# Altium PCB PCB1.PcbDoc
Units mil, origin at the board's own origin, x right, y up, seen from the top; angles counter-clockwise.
Board outline 3149.61 x 3937.01 mil, 2 copper layers (Top Layer, Bottom Layer); 80 components, 52 nets, 339 pads, 13 vias.
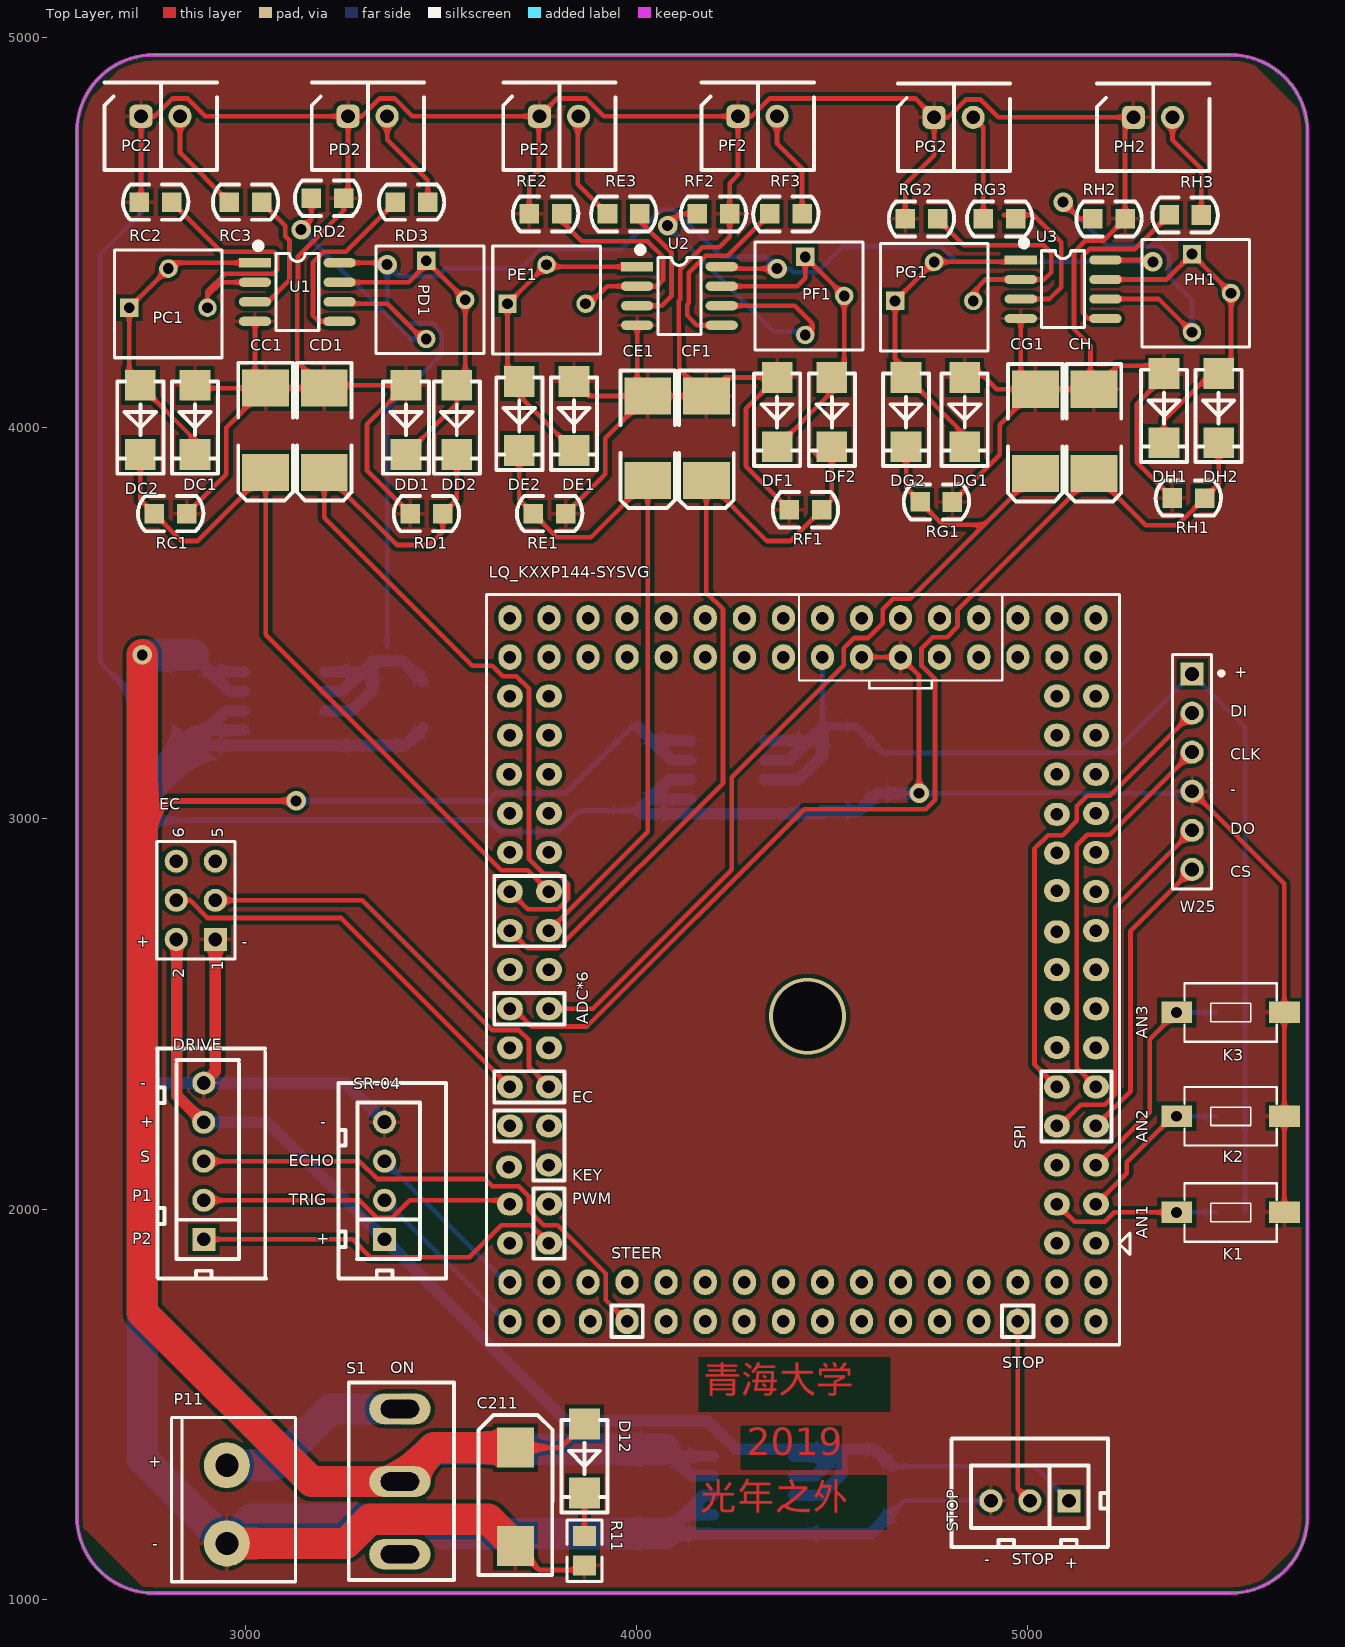
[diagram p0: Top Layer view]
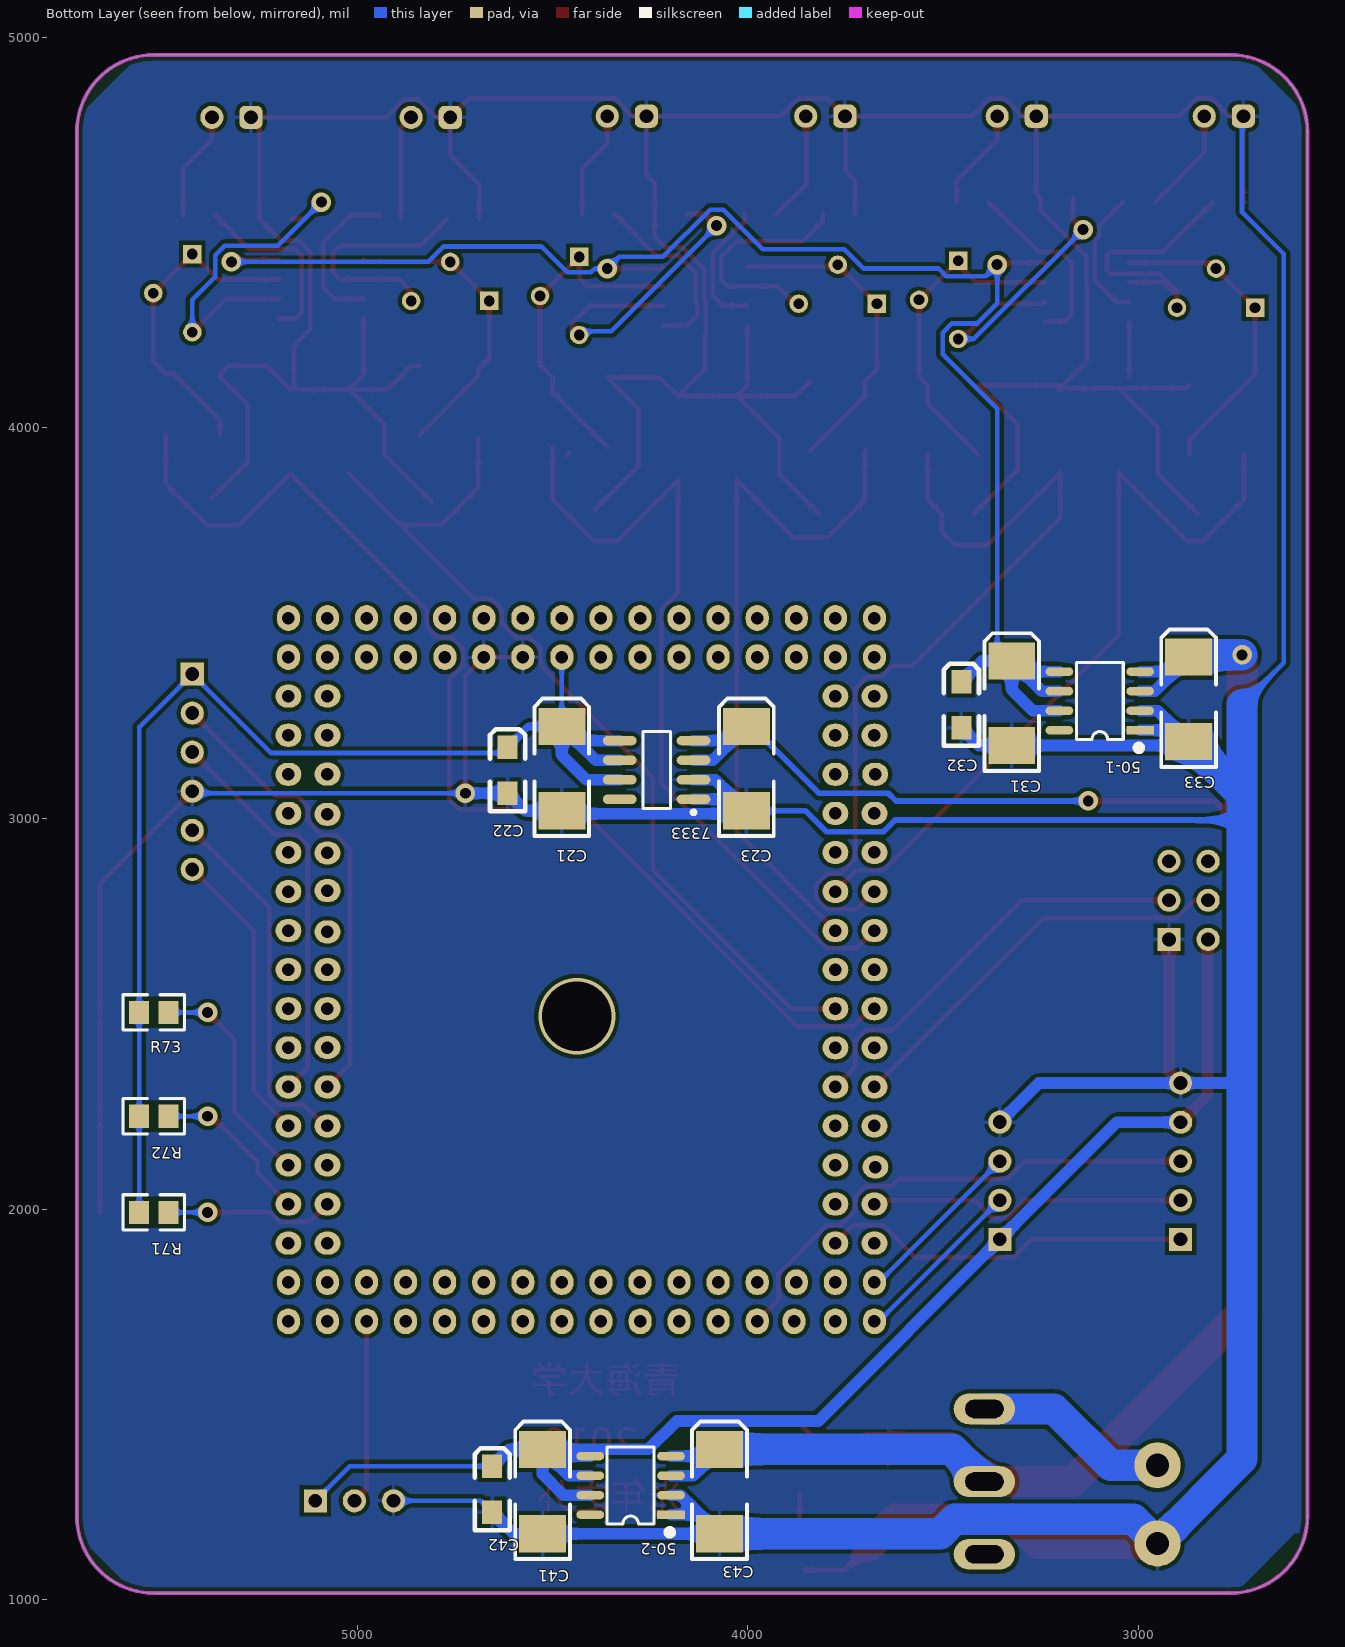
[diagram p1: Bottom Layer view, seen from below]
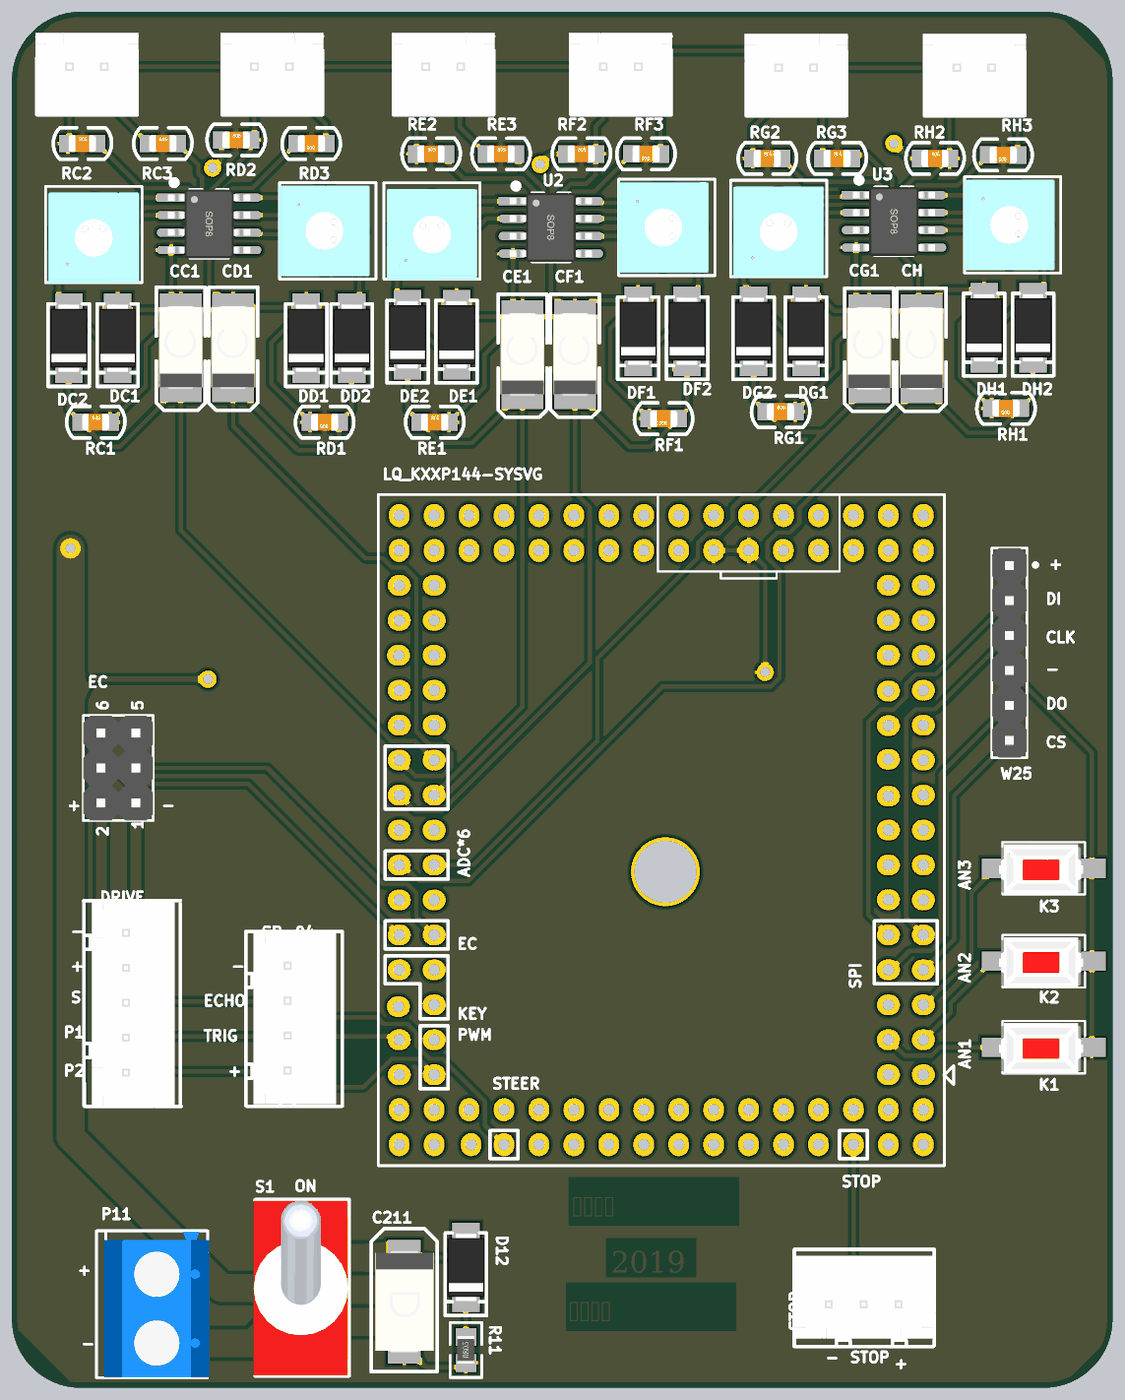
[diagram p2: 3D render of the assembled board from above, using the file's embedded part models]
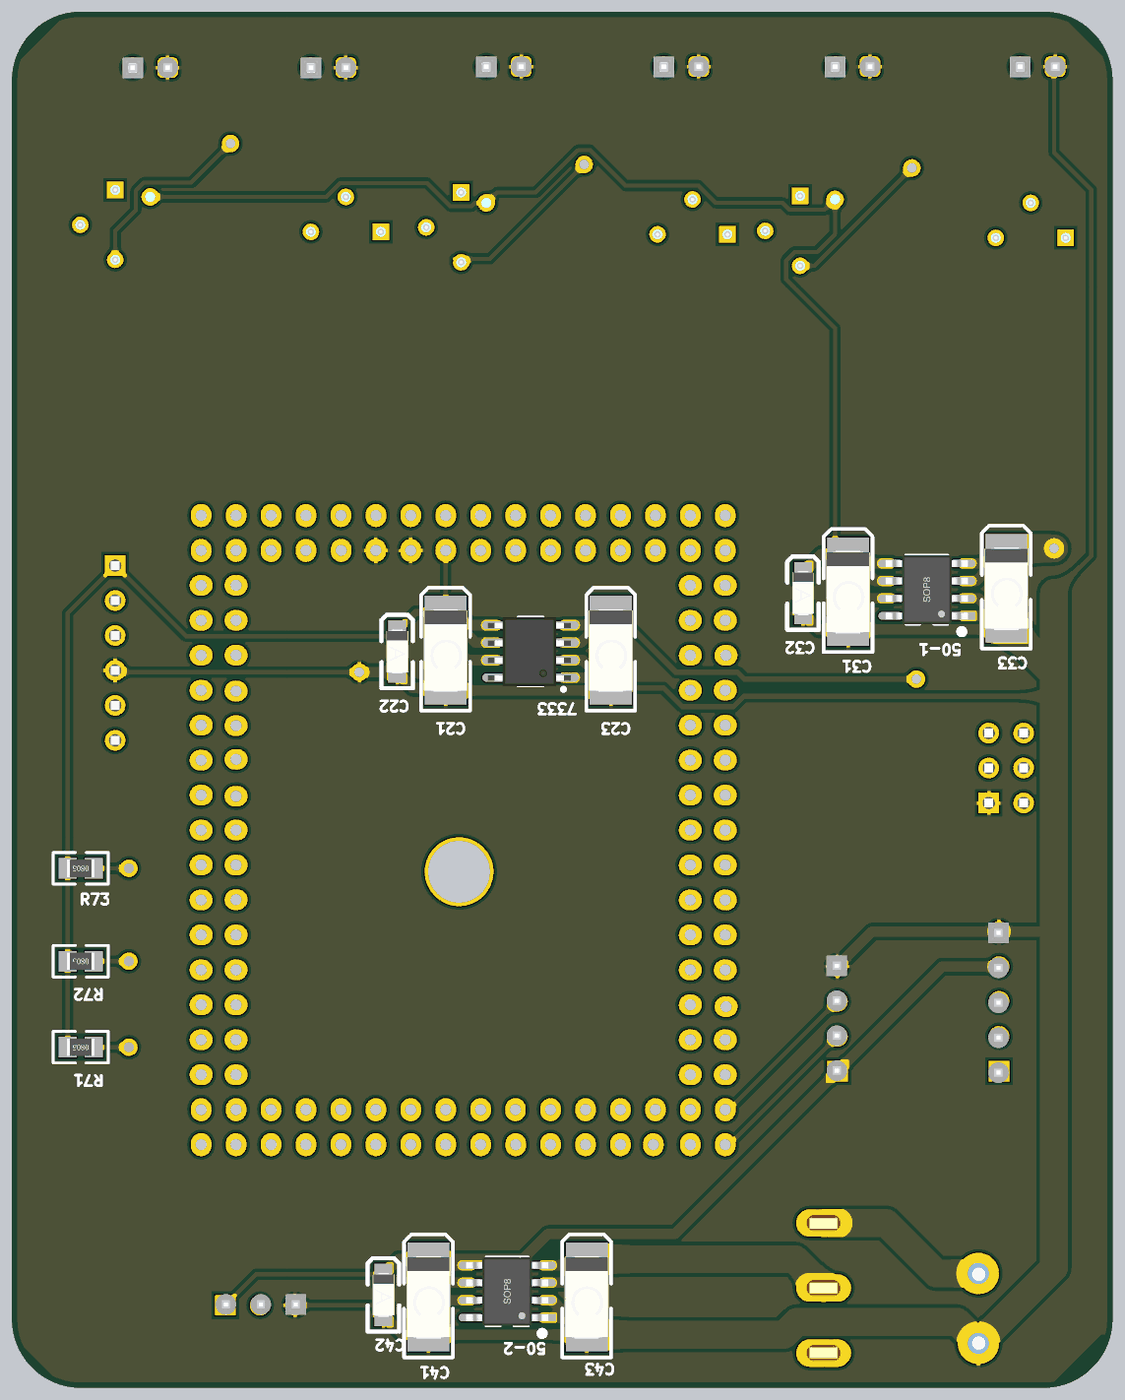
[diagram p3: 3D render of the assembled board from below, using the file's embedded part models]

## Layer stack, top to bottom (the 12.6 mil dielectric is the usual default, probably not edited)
Top Solder: solder mask 0.4, Solder Resist, Dk 3.5
Top Layer: signal copper 1.4
Dielectric 1: dielectric 12.6, FR-4, Dk 4.8
Bottom Layer: signal copper 1.4
Bottom Solder: solder mask 0.4, Solder Resist, Dk 3.5

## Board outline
2567.68,1214.09 2567.68,4757.4 cw(c2764.53,4757.4) 2764.53,4954.25 5520.43,4954.25 cw(c5520.43,4757.4) 5717.28,4757.4 5717.28,1214.09 cw(c5520.43,1214.09) 5520.43,1017.24 2764.53,1017.24 cw(c2764.53,1214.09)

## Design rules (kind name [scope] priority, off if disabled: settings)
Clearance [All] p1: gap=10
HoleSize [All] p1: absolutevalues=TRUE maxlimit=350 minlimit=1 maxpercent=80.000 minpercent=20.000
MinimumSolderMaskSliver [All] p1 off: minsoldermaskwidth=10
PolygonConnect [All] p1: connectstyle=Relief reliefconductorwidth=10 reliefentries=4 polygonreliefangle="90 Angle" airgapwidth=10
RoutingVias [All] p1: holewidth=28 width=50 viastyle="Through Hole" minholewidth=28 minwidth=50 maxholewidth=28 maxwidth=50
SilkToBoardRegionClearance [All] p1 off:
SilkToSilkClearance [All] p1 off: silktosilkclearance=10
SilkToSolderMaskClearance [IsPad] p1 off: minsilkscreentomaskgap=10 clearancetoexposedcopper=TRUE
SolderMaskExpansion [All] p1: expansion=4
Width [All] p1: maxlimit=100 minlimit=8 preferedwidth=12
25 further rules are at their usual default settings.

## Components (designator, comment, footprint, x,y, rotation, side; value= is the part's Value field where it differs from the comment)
50-1 "7350" SOP8_N 3099.17,3300.71 r0 bottom locked
50-2 "7350" SOP8_N 4299.96,1292.83 r0 bottom locked
7333 "7333" SO8_N 4233.43,3124.06 r0 bottom locked
AN1 "Button" SMT4*6*2.5 5520.43,1991.65 r180 top locked
AN2 "Button" SMT4*6*2.5 5520.43,2237.72 r180 top locked
AN3 "Button" SMT4*6*2.5 5520.43,2503.46 r180 top locked
C21 "Cap Pol3" C6032 4477.13,3123.54 r270 bottom locked
C22 "Cap Pol3" C3216 4614.92,3123.54 r270 bottom locked
C23 "Cap Pol3" C6032 4004.69,3123.54 r270 bottom locked
C31 "Cap Pol3" C6032 3325.55,3290.87 r270 bottom locked
C32 "Cap Pol3" C3216 3453.5,3290.87 r270 bottom locked
C33 "Cap Pol3" C6032 2872.8,3300.71 r270 bottom locked
C41 "Cap Pol3" C6032 4526.34,1273.15 r270 bottom locked
C42 "Cap Pol3" C3216 4654.29,1282.99 r270 bottom locked
C43 "Cap Pol3" C6032 4073.58,1273.15 r270 bottom locked
C211 "Cap Pol3" C7343 3689.72,1263.31 r270 top locked
CC1 "Cap Pol3" C6032 3051.77,3997.24 r90 top
CD1 "Cap Pol3" C6032 3201.77,3997.24 r90 top
CE1 "Cap Pol3" C6032 4029.77,3977.24 r90 top
CF1 "Cap Pol3" C6032 4179.77,3977.24 r90 top
CG1 "Cap Pol3" C6032 5021.77,3994.45 r90 top
CH "Cap Pol3" C6032 5171.77,3994.45 r90 top
D12 "LED1" SMA 3866.89,1361.73 r270 top locked
DC1 "4148" SMA 2870,4020 r270 top
DC2 "4148" SMA 2730,4020 r270 top
DD1 "4148" SMA 3410,4020 r270 top
DD2 "4148" SMA 3540,4020 r270 top
DE1 "4148" SMA 3840,4030 r270 top
DE2 "4148" SMA 3700,4030 r270 top
DF1 "4148" SMA 4360,4040 r270 top
DF2 "4148" SMA 4500,4040 r270 top
DG1 "4148" SMA 4840,4040 r270 top
DG2 "4148" SMA 4690,4040 r270 top
DH1 "4148" SMA 5350,4050 r270 top
DH2 "4148" SMA 5490,4050 r270 top
DRIVE "Header 5" HX2.54-5 2892.48,1922.76 r90 top locked
EC "Header 3X2" HDR2X3 2922.01,2690.47 r90 top locked
LQ_KXXP144-SYSVG "LQ_KXXP144-SYSVG" LQ_KXXP144-SYSVG 5175.94,1912.91 r90 top locked
P11 "Header 2" 2PIN-5.08B 2951.54,1144.41 r90 top locked
PC1 "RPot" VR_B1 2801.77,4297.24 r0 top
PC2 "Header 2" HX2.54-2 2731.77,4797.24 r0 top
PD1 "RPot" VR_B1 3451.77,4327.24 r270 top
PD2 "Header 2" HX2.54-2 3261.77,4797.24 r0 top
PE1 "RPot" VR_B1 3769.77,4307.24 r0 top
PE2 "Header 2" HX2.54-2 3751.77,4797.24 r0 top
PF1 "RPot" VR_B1 4421.77,4337.24 r270 top
PF2 "Header 2" HX2.54-2 4259.77,4797.24 r0 top
PG1 "RPot" VR_B1 4761.77,4314.45 r0 top
PG2 "Header 2" HX2.54-2 4761.77,4794.45 r0 top
PH1 "RPot" VR_B1 5411.77,4344.45 r270 top
PH2 "Header 2" HX2.54-2 5271.77,4794.45 r0 top
R11 "Res3" R0805 3866.89,1125.51 r90 top locked
R71 "Res3" R0805 5520.43,1991.65 r0 bottom locked
R72 "Res3" R0805 5520.43,2237.72 r0 bottom locked
R73 "Res3" R0805 5520.43,2503.46 r0 bottom locked
RC1 "Res Semi" C0805 2760,3780 r0 top
RC2 "Res Semi" C0805 2721.77,4577.24 r0 top
RC3 "Res Semi" C0805 2951.77,4577.24 r0 top
RD1 "Res Semi" C0805 3510,3780 r180 top
RD2 "Res Semi" C0805 3161.77,4587.24 r0 top
RD3 "Res Semi" C0805 3471.77,4577.24 r180 top
RE1 "Res Semi" C0805 3730,3780 r0 top
RE2 "Res Semi" C0805 3719.77,4547.24 r0 top
RE3 "Res Semi" C0805 3919.77,4547.24 r0 top
RF1 "Res Semi" C0805 4480,3790 r180 top
RF2 "Res Semi" C0805 4149.77,4547.24 r0 top
RF3 "Res Semi" C0805 4429.77,4547.24 r180 top
RG1 "Res Semi" C0805 4720,3810 r0 top
RG2 "Res Semi" C0805 4681.77,4534.45 r0 top
RG3 "Res Semi" C0805 4881.77,4534.45 r0 top
RH1 "Res Semi" C0805 5460,3820 r180 top
RH2 "Res Semi" C0805 5161.77,4534.45 r0 top
RH3 "Res Semi" C0805 5451.77,4544.45 r180 top
S1 "SW-SPST" SW-TO3 3394.45,1302.68 r180 top locked
SR-04 "Header 4" HX2.54-4 3355.08,1922.76 r90 top locked
STOP "Header 3" HX2.54-3 5107.05,1253.46 r180 top locked
U1 "LM358" SOP8_M 3131.77,4347.24 r0 top
U2 "LM358" SOP8_M 4109.77,4337.24 r0 top
U3 "LM358" SOP8_M 5091.77,4354.45 r0 top
W25 "MHDR1X6" HDR1X6 5422.01,3369.61 r270 top locked

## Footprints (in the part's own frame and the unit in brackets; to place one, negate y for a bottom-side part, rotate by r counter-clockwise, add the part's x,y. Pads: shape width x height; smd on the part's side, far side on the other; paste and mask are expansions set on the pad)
2PIN-5.08B [mm] "3A"
  round 3 hole 1.5: 1(0,0) 2(5.08,0)
  silkscreen extent -2.49,-4.47 8.18,3.61, body extent -2.48,-4.58 8.12,3.02, height 10
C0805 [mil]
  rect 50x50 smd: 1(6,0) 2(88.7,-0.1)
  silkscreen extent -36,-45 131,45, body extent 8,-24 87,25, height 30
C3216 [mil] "A型/1206"
  rect 60x51.18 smd: 1(-59,0) 2(59,0)
  silkscreen extent -105,-45 105,45, body extent -63,-31 63,32, height 63
C6032 [mil] "C型"
  rect 95x120 smd: 1(-112,1) 2(104,1)
  silkscreen extent -183,-69 169,71, body extent -121,-62 115,64, height 102
C7343 [mm] "D型"
  rect 2.6x2.4 smd: 1(-3.202,0.007) 2(3.198,0.007)
  silkscreen extent -5.32,-2.39 5.08,2.41, body extent -3.65,-2.12 3.65,2.18, height 2.9
HDR1X6 [mm] "Connector; Header; 6 Position"
  rect 1.5x1.5 hole 0.9: 1(0,0)
  round 1.5 hole 0.9: 2(2.54,0) 3(5.08,0) 4(7.62,0) 5(10.16,0) 6(12.7,0)
  silkscreen extent -1.27,-1.27 13.97,2.04, body extent -1.27,-1.27 13.97,1.27, height 8.54
HDR2X3 [mm] "Connector; Header; 3x2 Position"
  rect 1.5x1.5 hole 0.9: 1(0,0)
  round 1.5 hole 0.9: 2(0,2.54) 3(2.54,0) 4(2.54,2.54) 5(5.08,0) 6(5.08,2.54)
  silkscreen extent -1.27,-1.27 6.35,3.81, body extent -1.27,-1.27 6.35,3.81, height 8.54
HX2.54-2 [mm] "两针白色插座（已加焊）"
  rrect50% 1.5x1.5 hole 0.9: 1(0,0)
  round 1.5 hole 0.9: 2(2.54,0)
  silkscreen extent -2.36,-3.5 4.94,2.2, body extent -2.48,-3.55 5.02,2.45, height 7
HX2.54-3 [mm]
  rect 1.5x1.5 hole 0.9: 1(0,0)
  round 1.5 hole 0.9: 2(2.54,0) 3(5.08,0)
  silkscreen extent -2.54,-4.06 7.63,3, body extent -2.41,-3.58 7.59,2.42, height 7
HX2.54-4 [mm]
  rect 1.5x1.5 hole 0.9: 1(0,0)
  round 1.5 hole 0.9: 2(2.54,0) 3(5.08,0) 4(7.62,0)
  silkscreen extent -2.54,-4 10.16,3, body extent -2.4,-3.56 10.12,2.44, height 7
HX2.54-5 [mm]
  rect 1.5x1.5 hole 0.9: 1(0,0)
  round 1.5 hole 0.9: 2(2.54,0) 3(5.08,0) 4(7.607,0.006) 5(10.16,0)
  silkscreen extent -2.55,-4.06 12.42,3.05, body extent -2.56,-3.56 12.52,2.44, height 7.51
LQ_KXXP144-SYSVG [mil]
  oval 59x66 hole 32: 1(0,0) 2(0,100) 3(100,0) 4(100,100) 5(200,0) 6(200,100) 7(300,0) 8(300,100) 9(400,0) 10(400,100) 11(500,0) 12(500.79,100) 13(600,0) 14(600,100) 15(700,0) 16(700,100) 17(800,0) 18(796.85,100) 19(900,0) 20(902.36,100) 21(1000,0) 22(998.82,100) 23(1100,0) 24(1097.64,100) 25(1200,0) 26(1200.39,100) 27(1300,0) 28(1300,100) 29(1400,0) 30(1400.39,100) 63(1400,1500) 64(1400,1400) 65(1300,1500) 66(1300,1400) 67(1200,1501.97) 68(1200,1400) 69(1100,1500) 70(1100,1400) 71(1000,1500) 72(1000,1400) 73(900,1500) 74(900,1400) 75(800,1500) 76(800,1400) 77(700,1500) 78(700,1400) 79(600,1500) 80(600,1400) 81(500,1500) 82(500,1400) 83(400,1500) 84(400,1400) 85(300,1500) 86(300,1400) 87(194.88,1502.36) 88(200,1400) 89(100,1500) 90(100,1400) 91(0,1500) 92(0,1400)
  oval 66x59 hole 32: 31(1500,0) 32(1600,0) 33(1500,100) 34(1600,100) 35(1500,200) 36(1600,200) 37(1500,300) 38(1600,300) 39(1500,400.79) 40(1600,400) 41(1500,500) 42(1600,500.39) 43(1500,600) 44(1600,600) 45(1500,700) 46(1600,700) 47(1500,800) 48(1600,800) 49(1500,900) 50(1600,900) 51(1500,1000) 52(1600,1000) 53(1500,1100) 54(1600,1100) 55(1500,1200) 56(1600,1200) 57(1500,1300) 58(1600,1300) 59(1500,1400) 60(1600,1400) 61(1500,1500) 62(1600,1500) 93(-100,1500) 94(-200,1500) 95(-100,1400) 96(-200,1400) 97(-100,1300) 98(-200,1294.09) 99(-100,1200) 100(-200,1200) 101(-100,1100) 102(-200,1100) 103(-100,1000) 104(-200,1000) 105(-100,899.61) 106(-200,900.39) 107(-100,800) 108(-200,800) 109(-100,700) 110(-200,700) 111(-100,600) 112(-200,600) 113(-100,500) 114(-200,500) 115(-100,400) 116(-200,400) 117(-100,300) 118(-200,300) 119(-100,200) 120(-200,200) 121(-100,100) 122(-200,100) 123(-100,0) 124(-200,0)
  silkscreen extent -260,-87 1660,1560
R0805 [mm]
  rect 1.3x1.5 smd: 1(-0.95,0) 2(0.95,0)
  silkscreen extent -2,-1.15 2,1.15, body extent -1,-0.63 1,0.63, height 0.55
SMA [mm]
  rect 2x2 smd: 1(-2.25,0) 2(2.25,0)
  silkscreen extent -2.5,-1.5 3.5,1.5, body extent -2.5,-1.35 2.5,1.35, height 2.15
SMT4*6*2.5 [mm]
  rect 2x1.4 smd: 1(-3.5,0) 2(3.5,0)
  silkscreen extent -3,-1.9 3,1.9, body extent -2.85,-1.75 3.25,1.95, height 2.5
SO8_N [mm] "SOIC, 8-Leads, Body 4.9x3.9mm, Pitch 1.27mm, IPC Medium Density"
  oval 2.2x0.6 smd: 1(-2.4,1.905) 2(-2.4,0.635) 3(-2.4,-0.635) 4(-2.4,-1.905) 5(2.4,-1.905) 6(2.4,-0.635) 7(2.4,0.635) 8(2.4,1.905)
  silkscreen extent -2.52,-2.5 0.9,2.88, body extent -2.94,-2.48 3.1,2.54, height 1.6
SOP8_M [mm] "5*6*1.8mm（长宽高）"
  rect 2.1x0.6 smd: 1(-2.75,1.905)
  oval 2.1x0.6 smd: 2(-2.75,0.635) 3(-2.75,-0.635) 4(-2.75,-1.905) 5(2.75,-1.905) 6(2.75,-0.635) 7(2.75,0.635) 8(2.75,1.905)
  silkscreen extent -2.69,-2.5 1.4,3.15, body extent -3,-2.5 3,2.5, height 1.9
SOP8_N [mm] "5*6*1.8mm（长宽高）"
  rect 1.8x0.55 smd: 1(-2.625,1.905)
  oval 1.8x0.55 smd: 2(-2.625,0.635) 3(-2.625,-0.635) 4(-2.625,-1.905) 5(2.625,-1.905) 6(2.625,-0.635) 7(2.625,0.635) 8(2.625,1.905)
  silkscreen extent -2.69,-2.5 1.52,3.2, body extent -3,-2.5 3,2.5, height 1.9
SW-TO3 [mm]
  oval 4x2 hole 1.2 slot 2.5 at 0 deg: 1(0,-4.724) 2(0,0) 3(0,4.724)
  silkscreen extent -3.5,-6.43 3.33,6.39, body extent -3.43,-6.36 3.43,6.35, height 28.55
VR_B1 [mm] "Potentiometer; 3 Leads"
  rect 1.2x1.2 hole 0.7: 1(-2.54,0.254)
  round 1.2 hole 0.7: 2(0,2.794) 3(2.54,0.254)
  silkscreen extent -3.5,-3 3.5,4, body extent -3.3,-3.05 3.3,3.55, height 4.4

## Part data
C21 C22 C23 C31 C32 C33 C41 C42 C43 C211 CC1 CD1 CE1 CF1 CG1 CH: "Polarized Capacitor (Surface Mount)"
D12: library part LED3, "Typical BLUE SiC LED"
DC1 DC2 DD1 DD2 DE1 DE2 DF1 DF2 DG1 DG2 DH1 DH2: library part Diode, "Default Diode"
DRIVE: "Header, 5-Pin"
EC: "Header, 3-Pin, Dual row"
P11 PC2 PD2 PE2 PF2 PG2 PH2: "Header, 2-Pin"
PC1 PD1 PE1 PF1 PG1 PH1: "精密可调电阻"
R11 R71 R72 R73: "Resistor"
RC1 RC2 RC3 RD1 RD2 RD3 RE1 RE2 RE3 RF1 RF2 RF3 RG1 RG2 RG3 RH1 RH2 RH3: "Semiconductor Resistor"
S1: "Single-Pole, Single-Throw Switch"
SR-04: "Header, 4-Pin"
STOP: "Header, 3-Pin"
W25: "Header, 6-Pin"

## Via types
v1: diameter 50, hole 28, Top Layer to Bottom Layer, 12 vias
v2: diameter 196.85, hole 177.17, Top Layer to Bottom Layer, 1 vias

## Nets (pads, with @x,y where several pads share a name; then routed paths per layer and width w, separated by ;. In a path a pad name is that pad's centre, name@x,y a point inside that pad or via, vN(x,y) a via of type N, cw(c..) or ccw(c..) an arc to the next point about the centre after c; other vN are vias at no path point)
5V: 50-2.5 50-2.6 50-2.7 C41.1 C42.1 DRIVE.4 EC.2 SR-04.1 STOP.1 | length 3576
  Top Layer w30: EC.2 2823.58,2688.9 2823.58,2290.92 DRIVE.4
  Bottom Layer w12: C42.1 5018.52,1341.99 STOP.1
  Bottom Layer w30: DRIVE.4 3055.58,2222.26 SR-04.1 3820.19,1457.65 4182.07,1457.65 4254.57,1385.15 C41.1 ; 50-2.7 4471.81,1267.83 4525.34,1321.36 C41.1 ; 50-2.6 4458.02,1317.83 C41.1@4508.02,1367.83 ; 50-2.5 C41.1@4508.02,1367.83 ; C42.1 4611.13,1385.15 C41.1 ; C41.1@4508.02,1367.83 C41.1
ADC1_SE10: CC1.1 DC2.2 LQ_KXXP144-SYSVG.74 RC1.1 | length 1965.1
  Top Layer w12: DC2.2 2730,3816 RC1.1 2836,3710 2875.53,3710 CC1.1 3050.77,3470.24 3653.6,2867.41 3721.45,2867.41 LQ_KXXP144-SYSVG.74
ADC1_SE11: CD1.1 DD2.2 LQ_KXXP144-SYSVG.73 RD1.1 | length 2206.7
  Top Layer w12: DD2.2 3540,3816 RD1.1 3504,3734 3470,3700 3386.02,3700 CD1.1 3200.77,3769.23 3579.43,3390.57 3630.45,3390.57 3657.1,3363.91 3692.79,3363.91 3724.95,3331.76 3724.95,2896.07 3762.6,2858.41 3798.29,2858.41 3824.95,2831.76 3824.95,2794.07 3798.29,2767.41 3721.94,2767.41 3676.44,2812.91 LQ_KXXP144-SYSVG.73
ADC1_SE12: CE1.1 DE2.2 LQ_KXXP144-SYSVG.76 RE1.1 | length 1811.2
  Top Layer w12: DE2.2 3700,3816 RE1.1 3796,3720 3883.53,3720 CE1.1 4028.77,2965.74 LQ_KXXP144-SYSVG.76
ADC1_SE13: CF1.1 DF2.2 LQ_KXXP144-SYSVG.75 RF1.1 | length 2105.3
  Top Layer w12: LQ_KXXP144-SYSVG.75 3676.44,2712.91 3721.94,2667.41 3798.29,2667.41 4221.45,3090.57 4221.45,3535.26 4178.77,3577.93 CF1.1 4334.02,3710 4394,3710 RF1.1 4500,3816 DF2.2 ; 4455.77,3937.24 DF2.2@4461.77,3931.24
ADC1_SE14: CG1.1 DG2.2 LQ_KXXP144-SYSVG.80 RG1.1 | length 2361.4
  Top Layer w12: LQ_KXXP144-SYSVG.80 3887.44,2512.91 4243.45,2868.92 4243.45,3105.12 4530.45,3392.12 4530.45,3435.26 4557.1,3461.91 4592.79,3461.91 4630.05,3499.17 4630.05,3535.26 4656.7,3561.91 4700.24,3561.91 4890,3751.68 ; DG2.2@4690,3971.42 4690,3846 RG1.1 4784.32,3751.68 4890,3751.68 ; CG1.1 4890,3751.68
ADC1_SE15: CH.1 DH2.2 LQ_KXXP144-SYSVG.79 RH1.1 | length 2944.3
  Top Layer w12: LQ_KXXP144-SYSVG.79 3686.1,2512.91 3731.77,2467.24 3731.94,2467.41 3873.05,2467.41 4429.13,3023.49 4740.17,3023.49 4764.19,3047.51 4764.19,3355.78 4729.66,3390.31 4729.66,3435.26 4758.31,3463.91 4794.79,3463.91 4821.45,3490.57 4821.45,3533.12 CH.1 5303.22,3750 5384,3750 RH1.1 5490,3856 DH2.2@5490,3981.42
CLK: LQ_KXXP144-SYSVG.9 W25.3 | length 1032.9
  Top Layer w12: LQ_KXXP144-SYSVG.9 5126.73,2362.13 5126.73,2931.55 5153.6,2958.41 5210.82,2958.41 W25.3
CS: LQ_KXXP144-SYSVG.7 W25.6 | length 758.6
  Top Layer w12: LQ_KXXP144-SYSVG.7 5264.53,2301.5 5264.53,2712.13 W25.6
DI: LQ_KXXP144-SYSVG.10 W25.2 | length 1202.8
  Top Layer w12: LQ_KXXP144-SYSVG.10 5018.46,2370.39 5018.46,2922.1 5053.6,2957.23 5090.47,2957.23 5126.95,2993.7 5126.95,3031.76 5153.6,3058.41 5210.82,3058.41 W25.2
DO: LQ_KXXP144-SYSVG.8 W25.5 | length 939.8
  Top Layer w12: LQ_KXXP144-SYSVG.8 5082.24,2212.91 5136.74,2267.41 5198.29,2267.41 5224.95,2294.07 5224.95,2772.54 W25.5
ECA: EC.3 LQ_KXXP144-SYSVG.84 | length 1091.5
  Top Layer w12: EC.3 3298.39,2790.47 3630.45,2458.41 3698.29,2458.41 3724.95,2431.76 3724.95,2363.91 LQ_KXXP144-SYSVG.84
ECB: EC.4 LQ_KXXP144-SYSVG.83 | length 1051.7
  Top Layer w12: EC.4 2857.62,2790.47 2903.15,2744.94 3243.91,2744.94 LQ_KXXP144-SYSVG.83
ECHO: LQ_KXXP144-SYSVG.93 SR-04.3 | length 449.2
  Bottom Layer w12: SR-04.3 3664.92,1812.91 LQ_KXXP144-SYSVG.93
GND: 50-1.1 50-1.2 50-2.1 50-2.2 7333.1 7333.2 AN1.1 AN2.1 AN3.1 C21.2 C22.2 C23.2 C31.2 C32.2 C33.2 C41.2 C42.2 C43.2 C211.2 CC1.2 CD1.2 CE1.2 CF1.2 CG1.2 CH.2 DC1.1 DD1.1 DE1.1 DF1.1 DG1.1 DH1.1 DRIVE.5 EC.1 LQ_KXXP144-SYSVG.41 LQ_KXXP144-SYSVG.43 P11.1 PC2.1 PD2.1 PE2.1 PF2.1 PG2.1 PH2.1 R11.1 RC1.2 RC2.1 RD1.2 RD2.2 RE1.2 RE2.1 RF1.2 RF2.2 RG1.2 RG2.1 RH1.2 RH2.2 SR-04.4 STOP.3 U1.4 U2.4 U3.4 W25.4 | length 24372.6
  Top Layer w12: RC2.1 2731.77,4581.24 PC2.1 2767.39,4797.24 2812.91,4842.77 2850.63,4842.77 2896.16,4797.24 PD2.1 ; RC1.2 2950,3881.2 2950,4000.47 CC1.2 ; DC1.1 2877.34,4101.24 CC1.2 ; CC1.2@3023.5,4128.51 U1.4 ; CD1.2@3204.77,4097.24 CD1.2 ; RD1.2 3310,3891.4 3310,4008.58 DD1.1 3198.58,4108.58 CD1.2@3196.01,4106.01 ; C211.2 3751.1,1076.3 R11.1@3855.08,1076.3 ; RE2.1 3725.77,4633.24 3749.77,4657.24 PE2.1@3749.77,4797.24 ; PE2.1@3739.77,4817.24 PE2.1@3749.77,4807.24 ; RE1.2 3920,3881.2 3920,3972.47 CE1.2 ; DE1.1 3877.34,4081.24 CE1.2 ; U2.4 4001.5,4108.51 CE1.2 ; RF1.2 4280,3901.4 4280,4048.58 DF1.1 4226.11,4128.58 CF1.2 ; LQ_KXXP144-SYSVG.43 LQ_KXXP144-SYSVG.41 4723.19,3365.67 v1(4723.19,3064.49) ; RG2.1 4687.77,4623.24 4761.77,4697.24 PG2.1 ; RG1.2 4930,3931.2 4930,4007.68 CG1.2 ; DG1.1@4840,4158.58 4861.42,4158.58 4921.55,4098.45 CG1.2 ; U3.4 4983.5,4135.72 CG1.2 ; RH1.2 5280,3911.4 5280,4060 5350,4130 DH1.1 5330,4158.58 5230.9,4158.58 CH.2 CH.2@5161.77,4098.45 ; W25.4 5658.23,2833.39 AN3.1 AN2.1 AN1.1 ; CC1.2 CD1.2 ; CD1.2@3196.01,4106.01 CD1.2 ; CD1.2@3196.01,4106.01 3131.77,4170.24 3131.77,4366.13 3133.77,4368.13 3133.77,4439.24 3250.47,4555.94 RD2.2 3261.77,4598.44 PD2.1 ; PD2.1 3297.39,4797.24 3342.91,4842.77 3380.63,4842.77 3426.16,4797.24 PE2.1@3749.77,4797.24 ; PE2.1@3749.77,4797.24 PE2.1 3797.3,4842.77 3870.63,4842.77 3916.16,4797.24 PF2.1 ; CE1.2 CF1.2 ; CF1.2 4109.77,4150.24 4109.77,4237.45 4107.77,4239.45 4107.77,4324.13 4111.77,4328.13 4111.77,4405.95 4167.88,4462.05 4211.87,4462.05 4238.47,4488.66 RF2.2 4238.47,4625.94 4259.77,4647.24 PF2.1 ; PF2.1 4295.39,4797.24 4340.91,4842.77 4713.45,4842.77 PG2.1 ; PG2.1 4797.39,4794.45 4842.91,4839.98 4880.63,4839.98 4926.16,4794.45 PH2.1 5250.47,4773.15 RH2.2 5195.38,4479.26 5149.88,4479.26 5119.77,4449.15 5119.77,4251.64 5161.77,4209.64 CH.2@5161.77,4098.45 ; CG1.2 CH.2@5161.77,4098.45
  Top Layer w30: DRIVE.5 2922.01,2352.28 EC.1
  Top Layer w80: P11.1 3256.42,1144.41 3318.06,1206.05 3621.35,1206.05 C211.2
  Bottom Layer w12: PC2.1 2735,4794.02 2735,4551.44 2628.15,4444.59 2628.15,3398.39 2735,3291.54 ; C42.2 4683.76,1253.46 STOP.3 ; v1@4723.13,3064.54 v1(4723.19,3064.49) 5416.89,3064.49 W25.4
  Bottom Layer w15: 2735,2995.59 3623.3,2995.59 3652.98,2965.91 3798.91,2965.91 3852.54,3019.54 C23.2
  Bottom Layer w30: 2741.3,2322.76 DRIVE.5 3255.08,2322.76 SR-04.4 ; 50-1.1 C33.2@2900.8,3225.71 ; 50-1.2 2950.8,3275.71 C33.2@2900.8,3225.71 ; C32.2 3408.5,3186.87 C31.2 2881.64,3186.87 C33.2 C33.2@2900.8,3225.71 ; 7333.1 C23.2@4033.2,3049.06 ; 7333.2 4083.2,3099.06 C23.2@4033.2,3049.06 ; 50-2.1 4121.27,1217.83 ; 50-2.2 4171.27,1267.83 4121.27,1217.83 ; C42.2 4599.45,1169.15 C41.2 C43.2 4121.27,1217.83 ; v1@4723.13,3064.54 C22.2 4569.92,3019.54 C21.2 4476.13,3012.24 4010.98,3012.24 C23.2 C23.2@4033.2,3049.06
  Bottom Layer w80: 2735,3291.54 2735,3059.91 ; C33.2 2735,3059.91 ; C43.2 3507.74,1169.15 3470.84,1206.05 3013.17,1206.05 P11.1 2735,1360.94 2735,2995.59 2735,3059.91
KEY1: AN1.2 LQ_KXXP144-SYSVG.4 R71.1 | length 436
  Top Layer w12: LQ_KXXP144-SYSVG.4 5121.45,1967.41 5198.29,1967.41 5222.53,1991.65 v1(5382.64,1991.65)
  Bottom Layer w12: v1(5382.64,1991.65) R71.1
KEY2: AN2.2 LQ_KXXP144-SYSVG.3 R72.1 | length 416.6
  Top Layer w12: LQ_KXXP144-SYSVG.3 5254.69,2091.65 5254.69,2119.61 5372.8,2237.72 v1(5382.64,2237.72)
  Bottom Layer w12: v1(5382.64,2237.72) R72.1
KEY3: AN3.2 LQ_KXXP144-SYSVG.5 R73.1 | length 578.4
  Top Layer w12: LQ_KXXP144-SYSVG.5 5179.09,2112.91 5313.74,2247.56 5313.74,2434.57 v1(5382.64,2503.46)
  Bottom Layer w12: v1(5382.64,2503.46) R73.1
NetD12_2: D12.2 R11.2 | length 110.2
  Top Layer w12: R11.2 D12.2
NetDC1_2: DC1.2 DC2.1 PC1.1 PC1.2 U1.1 | length 814.9
  Top Layer w12: DC1.2 2870,3968.58 DC2.1 2701.77,4136.81 PC1.1 PC1.2 2816.77,4422.24 U1.1
NetDD1_2: DD1.2 DD2.1 PD1.1 PD1.2 U1.7 | length 850.5
  Top Layer w12: U1.7 3416.77,4372.24 3461.77,4417.24 PD1.1 PD1.2 3561.77,4130.35 DD2.1 3540,4061.42 DD1.2
NetDE1_2: DE1.2 DE2.1 PE1.1 PE1.2 U2.1 | length 821.6
  Top Layer w12: DE1.2 3700,4081.42 DE2.1 3669.77,4148.81 PE1.1 PE1.2 3774.77,4412.24 U2.1
NetDF1_2: DF1.2 DF2.1 PF1.1 PF1.2 U2.7 | length 875.4
  Top Layer w12: U2.7 4411.77,4362.24 4431.77,4382.24 PF1.1 PF1.2 4531.77,4160.35 DF2.1 4500,4091.42 DF1.2
NetDG1_2: DG1.2 DG2.1 PG1.1 PG1.2 U3.1 | length 782.1
  Top Layer w12: DG1.2@4840,3981.42 4690,4131.42 4690,4148.58 4661.77,4176.81 PG1.1 PG1.2 4978.5,4424.45 U3.1
NetDH1_2: DH1.2 DH2.1 PH1.1 PH1.2 U3.7 | length 836
  Top Layer w12: U3.7 5356.77,4379.45 PH1.1 PH1.2 5521.77,4170.35 DH2.1 5470,4138.58 5350,4018.58 DH1.2@5350,3981.42
NetP11_2: P11.2 S1.1 | length 502.7
  Bottom Layer w80: P11.2 3072.01,1344.41 3216.28,1488.68 S1.1
NetPC1_3: PC1.3 RC2.2 U1.2 | length 743.6
  Top Layer w12: RC2.2 2937.56,4450.06 3071.47,4450.06 3080.84,4440.68 3080.84,4403.81 3071.47,4394.43 2947.07,4394.43 2901.77,4349.14 2901.77,4337.24 ; PC1.3 2901.77,4337.24 ; U1.2 2936.77,4372.24 2901.77,4337.24
NetPC2_2: PC2.2 RC3.1 | length 272.2
  Top Layer w12: PC2.2 2831.77,4703.24 RC3.1
NetPD1_3: PD1.3 RD2.1 U1.6 | length 787.8
  Top Layer w12: v1(3141.77,4507.24) 3167.77,4533.24 RD2.1 ; U1.6 3245.04,4317.24 3361.77,4317.24 3451.77,4227.24 PD1.3
  Bottom Layer w12: v1(3141.77,4507.24) 3421.77,4227.24 PD1.3
NetPD2_2: PD2.2 RD3.1 | length 263.1
  Top Layer w12: PD2.2 3361.77,4737.24 3465.77,4633.24 RD3.1
NetPE1_3: PE1.3 RE2.2 U2.2 | length 600.4
  Top Layer w12: RE2.2@3809.39,4546.22 RE2.2 3808.47,4528.54 3859.77,4477.24 4028.66,4477.24 4029.22,4476.69 4029.22,4475.8 4067.77,4437.24 4067.77,4377.24 4052.77,4362.24 U2.2 3924.77,4362.24 3879.77,4317.24 PE1.3
NetPE2_2: PE2.2 RE3.1 | length 281.5
  Top Layer w12: PE2.2@3849.77,4797.24 3849.77,4623.24 RE3.1
NetPF1_3: PF1.3 RF2.1 U2.6 | length 840.6
  Top Layer w12: v1(4079.77,4517.24) 4109.77,4547.24 RF2.1 ; U2.6 4404.77,4312.24 4449.77,4267.24 PF1.3@4449.77,4247.24
  Bottom Layer w12: v1(4079.77,4517.24) 4349.77,4247.24 PF1.3@4449.77,4247.24
NetPF2_2: PF2.2 RF3.1 | length 276.5
  Top Layer w12: PF2.2 4359.77,4727.24 4423.77,4663.24 RF3.1
NetPG1_3: PG1.3 RG2.2 U3.2 | length 620.9
  Top Layer w12: RG2.2 4837.58,4467.24 5041.77,4467.24 5061.77,4447.24 5061.77,4397.24 5043.98,4379.45 U3.2 4893.98,4379.45 4861.77,4347.24 PG1.3
NetPG2_2: PG2.2 RG3.1 | length 270.8
  Top Layer w12: PG2.2 4887.77,4768.45 RG3.1
NetPH1_3: PH1.3 RH2.1 U3.6 | length 899.3
  Top Layer w12: v1(5091.77,4577.24) 5134.57,4534.45 RH2.1 ; U3.6 5336.77,4329.45 PH1.3
  Bottom Layer w12: v1(5091.77,4577.24) 5203.57,4465.45 5338.75,4465.45 5362.77,4441.43 5362.77,4386.24 5421.77,4327.24 PH1.3
NetPH2_2: PH2.2 RH3.1 | length 280.7
  Top Layer w12: PH2.2 5371.77,4737.24 5445.77,4663.24 RH3.1
NetRC3_2: RC3.2 U1.3 | length 340.5
  Top Layer w12: U1.3 3056.77,4322.24 3111.77,4377.24 3111.77,4479.26 3100.77,4490.26 3100.77,4516.84 RC3.2
NetRD3_2: RD3.2 U1.5 | length 485.4
  Top Layer w12: U1.5 3186.77,4272.24 3171.77,4287.24 3171.77,4422.83 3198.99,4450.06 3255.78,4450.06 RD3.2
NetRE3_2: RE3.2 U2.3 | length 342.2
  Top Layer w12: U2.3 4064.77,4312.24 4089.77,4337.24 4089.77,4447.24 4008.47,4528.54 RE3.2
NetRF3_2: RF3.2 U2.5 | length 479.5
  Top Layer w12: U2.5 4154.77,4262.24 4129.77,4287.24 4129.77,4315.02 4133.77,4319.02 4133.77,4396.83 4176.99,4440.05 4233.78,4440.05 RF3.2
NetRG3_2: RG3.2 U3.3 | length 405.9
  Top Layer w12: 4940.47,4544.35 5016.87,4544.35 5086.77,4474.45 5086.77,4359.45 5056.77,4329.45 U3.3
NetRH3_2: RH3.2 U3.5 | length 474.7
  Top Layer w12: U3.5 5156.77,4279.45 5141.77,4294.45 5141.77,4440.04 5158.99,4457.26 5275.78,4457.26 RH3.2
PWM1: DRIVE.2 LQ_KXXP144-SYSVG.89 | length 825.3
  Top Layer w12: DRIVE.2 3290.69,2022.76 3336.22,1977.23 3373.94,1977.23 3419.46,2022.76 3666.1,2022.76 LQ_KXXP144-SYSVG.89
PWM2: DRIVE.1 LQ_KXXP144-SYSVG.92 | length 954.8
  Top Layer w12: DRIVE.1 3273.4,1922.76 3318.92,1877.23 3572.41,1877.23 3653.6,1958.41 3730.45,1958.41 LQ_KXXP144-SYSVG.92
STEER: DRIVE.3 LQ_KXXP144-SYSVG.100 | length 1313.9
  Top Layer w12: DRIVE.3 3290.69,2122.76 3336.22,2077.23 3611.63,2077.23 3630.45,2058.41 3698.29,2058.41 3724.95,2031.76 3724.95,1996.07 3762.6,1958.41 3798.29,1958.41 3921.45,1835.26 3921.45,1767.41 LQ_KXXP144-SYSVG.100
STOP: LQ_KXXP144-SYSVG.120 STOP.2 | length 472.3
  Top Layer w12: LQ_KXXP144-SYSVG.120 4975.95,1284.57 STOP.2
TRIG: LQ_KXXP144-SYSVG.94 SR-04.2 | length 449.2
  Bottom Layer w12: SR-04.2 3664.92,1712.91 LQ_KXXP144-SYSVG.94
VB: 50-1.3 50-1.4 50-2.3 50-2.4 7333.3 7333.4 C23.1 C33.1 C43.1 C211.1 D12.1 S1.2 | length 6058.9
  Top Layer w12: C211.1 3805.95,1389.37 D12.1
  Top Layer w15: 2735,2975.91 2803.9,3044.8 v1(3128.7,3044.8)
  Top Layer w80: v1(2735,3418.82) 2735,2975.91 2735,1735.75 3168.07,1302.68 S1.2 3481.14,1389.37 C211.1
  Bottom Layer w12: C23.1@3988.73,3235.54 C23.1
  Bottom Layer w15: v1(3128.7,3044.8) 3620.83,3044.8 3640.51,3064.49 3817.68,3064.49 C23.1@3988.73,3235.54
  Bottom Layer w20: C43.1 C43.1@4089.9,1367.83
  Bottom Layer w30: C33.1 C33.1@2908.8,3375.71 ; 50-1.3 2958.8,3325.71 C33.1@2908.8,3375.71 ; 50-1.4 C33.1@2908.8,3375.71 ; C23.1 C23.1@4040.17,3199.06 ; 7333.3 4090.17,3149.06 C23.1@4040.17,3199.06 ; 7333.4 C23.1@4040.17,3199.06 ; 50-2.3 4139.9,1317.83 4089.9,1367.83 50-2.4
  Bottom Layer w40: C33.1@2865.69,3418.82 C33.1
  Bottom Layer w80: v1(2735,3418.82) C33.1@2865.69,3418.82 ; S1.2 3476.92,1385.15 C43.1
VCC: 7333.5 7333.6 7333.7 C21.1 C22.1 LQ_KXXP144-SYSVG.45 R71.2 R72.2 R73.2 W25.1 | length 3212.9
  Bottom Layer w12: C21.1 LQ_KXXP144-SYSVG.45@4476.13,3412.73 ; C22.1 4630.05,3167.41 5219.82,3167.41 W25.1 5557.84,3233.78 R73.2 R72.2 R71.2
  Bottom Layer w20: C21.1 4561.92,3235.54 C22.1
  Bottom Layer w30: 7333.7 4413.27,3099.06 4476.13,3161.91 C21.1 C21.1@4439.64,3199.06 ; 7333.6 4389.64,3149.06 C21.1@4439.64,3199.06 ; 7333.5 C21.1@4439.64,3199.06
VDD: 50-1.5 50-1.6 50-1.7 C31.1 C32.1 U1.8 U2.8 U3.8 | length 4293.3
  Top Layer w12: U1.8 3356.77,4422.24 v1(3361.77,4417.24) ; U2.8 4223.04,4407.24 v1(4359.77,4407.24) ; U3.8 5316.77,4429.45 v1(5321.77,4424.45)
  Bottom Layer w12: C31.1@3361.77,3440.09 3361.77,4048 3501.39,4187.62 3501.39,4243.66 3478.18,4266.87 3413.26,4266.87 3361.77,4318.36 v1(3361.77,4417.24) 3391.39,4387.62 3492.02,4387.62 3512.02,4407.62 3704.12,4407.62 3753.36,4456.87 3961.41,4456.87 4062.79,4558.24 4096.75,4558.24 4217.75,4437.24 4329.77,4437.24 v1(4359.77,4407.24) 4391.9,4407.24 4401.52,4397.62 4462.02,4397.62 4528.47,4464.07 4778.18,4464.07 4817.8,4424.45 v1(5321.77,4424.45)
  Bottom Layer w30: 50-1.7 3271.02,3275.71 3324.55,3329.24 C31.1 ; 50-1.6 3247.39,3325.71 C31.1@3297.39,3375.71 ; 50-1.5 C31.1@3297.39,3375.71 ; C32.1 3400.5,3402.87 C31.1 ; C31.1@3297.39,3375.71 C31.1
pads on no net: 50-1.8 50-2.8 7333.8 EC.5 EC.6 LQ_KXXP144-SYSVG.1 LQ_KXXP144-SYSVG.2 LQ_KXXP144-SYSVG.6 LQ_KXXP144-SYSVG.11 LQ_KXXP144-SYSVG.12 LQ_KXXP144-SYSVG.13 LQ_KXXP144-SYSVG.14 LQ_KXXP144-SYSVG.15 LQ_KXXP144-SYSVG.16 LQ_KXXP144-SYSVG.17 LQ_KXXP144-SYSVG.18 LQ_KXXP144-SYSVG.19 LQ_KXXP144-SYSVG.20 LQ_KXXP144-SYSVG.21 LQ_KXXP144-SYSVG.22 LQ_KXXP144-SYSVG.23 LQ_KXXP144-SYSVG.24 LQ_KXXP144-SYSVG.25 LQ_KXXP144-SYSVG.26 LQ_KXXP144-SYSVG.27 LQ_KXXP144-SYSVG.28 LQ_KXXP144-SYSVG.29 LQ_KXXP144-SYSVG.30 LQ_KXXP144-SYSVG.31 LQ_KXXP144-SYSVG.32 LQ_KXXP144-SYSVG.33 LQ_KXXP144-SYSVG.34 LQ_KXXP144-SYSVG.35 LQ_KXXP144-SYSVG.36 LQ_KXXP144-SYSVG.37 LQ_KXXP144-SYSVG.38 LQ_KXXP144-SYSVG.39 LQ_KXXP144-SYSVG.40 LQ_KXXP144-SYSVG.42 LQ_KXXP144-SYSVG.44 LQ_KXXP144-SYSVG.46 LQ_KXXP144-SYSVG.47 LQ_KXXP144-SYSVG.48 LQ_KXXP144-SYSVG.49 LQ_KXXP144-SYSVG.50 LQ_KXXP144-SYSVG.51 LQ_KXXP144-SYSVG.52 LQ_KXXP144-SYSVG.53 LQ_KXXP144-SYSVG.54 LQ_KXXP144-SYSVG.55 LQ_KXXP144-SYSVG.56 LQ_KXXP144-SYSVG.57 LQ_KXXP144-SYSVG.58 LQ_KXXP144-SYSVG.59 LQ_KXXP144-SYSVG.60 LQ_KXXP144-SYSVG.61 LQ_KXXP144-SYSVG.62 LQ_KXXP144-SYSVG.63 LQ_KXXP144-SYSVG.64 LQ_KXXP144-SYSVG.65 LQ_KXXP144-SYSVG.66 LQ_KXXP144-SYSVG.67 LQ_KXXP144-SYSVG.68 LQ_KXXP144-SYSVG.69 LQ_KXXP144-SYSVG.70 LQ_KXXP144-SYSVG.71 LQ_KXXP144-SYSVG.72 LQ_KXXP144-SYSVG.77 LQ_KXXP144-SYSVG.78 LQ_KXXP144-SYSVG.81 LQ_KXXP144-SYSVG.82 LQ_KXXP144-SYSVG.85 LQ_KXXP144-SYSVG.86 LQ_KXXP144-SYSVG.87 LQ_KXXP144-SYSVG.88 LQ_KXXP144-SYSVG.90 LQ_KXXP144-SYSVG.91 LQ_KXXP144-SYSVG.95 LQ_KXXP144-SYSVG.96 LQ_KXXP144-SYSVG.97 LQ_KXXP144-SYSVG.98 LQ_KXXP144-SYSVG.99 LQ_KXXP144-SYSVG.101 LQ_KXXP144-SYSVG.102 LQ_KXXP144-SYSVG.103 LQ_KXXP144-SYSVG.104 LQ_KXXP144-SYSVG.105 LQ_KXXP144-SYSVG.106 LQ_KXXP144-SYSVG.107 LQ_KXXP144-SYSVG.108 LQ_KXXP144-SYSVG.109 LQ_KXXP144-SYSVG.110 LQ_KXXP144-SYSVG.111 LQ_KXXP144-SYSVG.112 LQ_KXXP144-SYSVG.113 LQ_KXXP144-SYSVG.114 LQ_KXXP144-SYSVG.115 LQ_KXXP144-SYSVG.116 LQ_KXXP144-SYSVG.117 LQ_KXXP144-SYSVG.118 LQ_KXXP144-SYSVG.119 LQ_KXXP144-SYSVG.121 LQ_KXXP144-SYSVG.122 LQ_KXXP144-SYSVG.123 LQ_KXXP144-SYSVG.124 S1.3
copper on no net:
  other v2: 4437.76,2493.62

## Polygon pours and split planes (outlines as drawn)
GND on Top Layer "Bottom Layer-No Net" (solid, remove dead copper, pour order 6): 2730,4950 2710,4950 2570,4810 2570,1180 2590,1180 2750,1020 5550,1020 5570,1020 5720,1170 5720,4790 5550,4960 2730,4960
GND on Bottom Layer "Bottom Layer-No Net" (solid, remove dead copper, pour order 8): 2730,4950 2720,4950 2570,4800 2580,4790 2580,1170 2600,1170 2750,1020 5560,1020 5570,1020 5710,1160 5710,4790 5710,4800 5560,4950 2730,4950

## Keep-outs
Keep-Out Layer:
  the board outline again, w10

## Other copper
Top Layer:
  text "青海大学" at 4171.77,1507.24 h120
  text "2019" at 4281.77,1347.24 h120
  text "光年之外" at 4161.77,1207.24 h120

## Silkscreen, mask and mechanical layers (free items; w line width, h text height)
Top Overlay:
  text "+" at 5530,3360 h30
  text "DI" at 5520,3260 h30
  text "CLK" at 5520,3150 h30
  text "-" at 5520,3060 h30
  text "DO" at 5520,2960 h30
  text "CS" at 5520,2850 h30
  text "+" at 2720,2670 h30
  text "-" at 2990,2670 h30
  text "K3" at 5500,2380 h30
  text "-" at 2730,2310 h30
  text "+" at 2730,2210 h30
  text "-" at 3190,2210 h30
  text "S" at 2730,2120 h30
  text "K2" at 5500,2120 h30
  text "ECHO" at 3110,2110 h30
  text "P1" at 2710,2020 h30
  text "TRIG" at 3110,2010 h30
  text "P2" at 2710,1910 h30
  text "+" at 3180,1910 h30
  text "K1" at 5500,1870 h30
  text "ON" at 3370,1580 h30
  text "+" at 2750,1340 h30
  text "-" at 2760,1130 h30
  text "+" at 5100,1110 h30 r270
  text "-" at 4890,1090 h30
  text "STOP" at 4960,1090 h30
